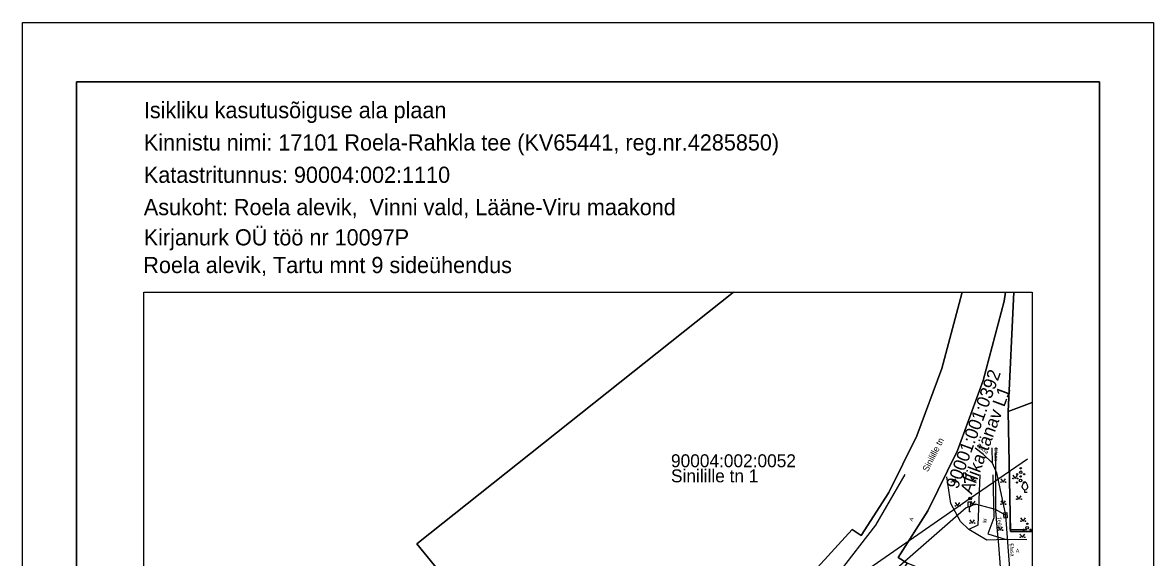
# Model space of a CAD drawing. Extents: x 648017 to 648227, y 6561313 to 6561610.
# Drawn here: x 648016.8 to 648226.8, y 6561510.6 to 6561609.9 of the extents above; entities that cross this region are included whole.
import ezdxf

# ---------------------------------------------------------------- set-up
doc = ezdxf.new("R2010")
doc.units = 0
for name, color, linetype in [('AED', 7, 'Continuous'), ('HALJASTUS', 7, 'Continuous'), ('KPOHULIIN', 7, 'Continuous'), ('LIIKLUS', 7, 'Continuous'), ('PIIR', 7, 'Continuous'), ('POST', 7, 'Continuous'), ('PR_SIDE', 7, 'Continuous'), ('PUU', 7, 'Continuous'), ('SIRAJATIS', 7, 'Continuous'), ('SITRASS', 7, 'Continuous'), ('TEE', 7, 'Continuous'), ('VORMISTUS', 7, 'Continuous')]:
    doc.layers.add(name, color=color, linetype=linetype)

msp = doc.modelspace()

# ---------------------------------------------------------------- linework, layer by layer
at = {"layer": 'AED'}
msp.add_lwpolyline([(648200.07, 6561526.28), (648200.12, 6561515.79), (648203.26, 6561515.79)], dxfattribs=at)
at = {"layer": 'HALJASTUS'}
for p, q in [((648200.65, 6561525.89), (648201.12, 6561525.28)), ((648201.12, 6561525.28), (648201.56, 6561525.89)), ((648189.19, 6561525.23), (648189.65, 6561524.63)), ((648189.65, 6561524.63), (648190.1, 6561525.23)), ((648192.79, 6561525.55), (648193.26, 6561524.94)), ((648193.26, 6561524.94), (648193.7, 6561525.55)), ((648198.42, 6561525.21), (648198.88, 6561524.61)), ((648198.88, 6561524.61), (648199.32, 6561525.21)), ((648201.35, 6561522.04), (648201.81, 6561521.44)), ((648201.81, 6561521.44), (648202.25, 6561522.04)), ((648189.94, 6561520.8), (648190.41, 6561520.19)), ((648190.41, 6561520.19), (648190.85, 6561520.8)), ((648192.79, 6561521.07), (648193.26, 6561520.47)), ((648193.26, 6561520.47), (648193.7, 6561521.07)), ((648198.42, 6561521.11), (648198.88, 6561520.51)), ((648198.88, 6561520.51), (648199.32, 6561521.11)), ((648192.68, 6561517.61), (648193.14, 6561517)), ((648193.14, 6561517), (648193.58, 6561517.61)), ((648202.12, 6561517.96), (648202.58, 6561517.36)), ((648202.58, 6561517.36), (648203.03, 6561517.96)), ((648197.86, 6561516.3), (648198.33, 6561515.69)), ((648198.33, 6561515.69), (648198.77, 6561516.3)), ((648202, 6561514.97), (648202.46, 6561514.37)), ((648202.46, 6561514.37), (648202.91, 6561514.97))]:
    msp.add_line(p, q, dxfattribs=at)
for centre in [(648189.25, 6561524.63), (648190.08, 6561524.63), (648192.86, 6561524.94), (648193.68, 6561524.94), (648198.48, 6561524.61), (648199.31, 6561524.61), (648200.72, 6561525.28), (648201.54, 6561525.28), (648201.41, 6561521.44), (648202.24, 6561521.44), (648190.01, 6561520.19), (648190.83, 6561520.19), (648192.86, 6561520.47), (648193.68, 6561520.47), (648198.48, 6561520.51), (648199.31, 6561520.51), (648202.18, 6561517.36), (648203.01, 6561517.36), (648192.74, 6561517), (648193.57, 6561517), (648197.92, 6561515.69), (648198.75, 6561515.69), (648202.06, 6561514.37), (648202.89, 6561514.37)]:
    msp.add_circle(centre, 0.055, dxfattribs=at)
at = {"layer": 'KPOHULIIN'}
msp.add_lwpolyline([(648203.38, 6561528.86), (648192.77, 6561521.55), (648147, 6561489.82)], dxfattribs=at)
at = {"layer": 'LIIKLUS'}
for p, q in [((648191.43, 6561526.29), (648191.43, 6561525.44)), ((648191.93, 6561526.29), (648191.43, 6561526.29)), ((648191.93, 6561526.29), (648191.93, 6561525.44)), ((648191.93, 6561525.44), (648191.43, 6561525.44)), ((648191.68, 6561525.44), (648191.68, 6561524.54)), ((648191.93, 6561524.54), (648191.68, 6561524.54)), ((648192.29, 6561520.86), (648192.29, 6561520.01)), ((648192.79, 6561520.86), (648192.29, 6561520.86)), ((648192.79, 6561520.01), (648192.29, 6561520.01)), ((648192.54, 6561520.01), (648192.54, 6561519.11)), ((648192.79, 6561520.86), (648192.79, 6561520.01)), ((648192.79, 6561519.11), (648192.54, 6561519.11))]:
    msp.add_line(p, q, dxfattribs=at)
at = {"layer": 'PIIR'}
for points in [[(648199.34, 6561559.88), (648199.07, 6561558.2), (648195.16, 6561543.45), (648190.37, 6561530.46), (648184.89, 6561519.28), (648179.37, 6561510.62), (648181.07, 6561509.57), (648180.15, 6561508.27), (648175.42, 6561502.2), (648170.88, 6561497.65), (648163.17, 6561490.84), (648148.46, 6561478.24), (648130.76, 6561463.29), (648079.41, 6561420.36), (648069.33, 6561411.95), (648039.27, 6561388.87)], [(648148.78, 6561559.88), (648090, 6561513.15), (648123.09, 6561472.56), (648039.27, 6561403.33)], [(648039.27, 6561403.33), (648123.09, 6561472.56), (648162.4, 6561506.57), (648170.84, 6561515.84), (648172.53, 6561514.72), (648177.65, 6561522.71), (648182.83, 6561533.2), (648187.47, 6561545.71), (648191.21, 6561559.62), (648191.24, 6561559.88)], [(648191.24, 6561559.88), (648191.21, 6561559.62), (648187.47, 6561545.71), (648182.83, 6561533.2), (648177.65, 6561522.71), (648172.53, 6561514.72), (648170.84, 6561515.84), (648162.4, 6561506.57), (648123.09, 6561472.56), (648090, 6561513.15), (648148.78, 6561559.88)], [(648204.28, 6561507.58), (648196.49, 6561507.4), (648190.43, 6561507.33), (648185.28, 6561507.91), (648181.07, 6561509.57), (648179.37, 6561510.62), (648184.89, 6561519.28), (648190.37, 6561530.46), (648195.16, 6561543.45), (648199.07, 6561558.2), (648199.34, 6561559.88)], [(648200.88, 6561559.88), (648199.82, 6561537.73), (648200.23, 6561515.42), (648204.28, 6561515.45)], [(648204.28, 6561539.37), (648199.82, 6561537.73), (648200.88, 6561559.88)], [(648204.28, 6561515.45), (648200.23, 6561515.42), (648199.82, 6561537.73), (648204.28, 6561539.37)]]:
    msp.add_lwpolyline(points, dxfattribs=at)
at = {"layer": 'POST'}
msp.add_circle((648192.77, 6561521.55), 0.25, dxfattribs=at)
at = {"layer": 'PR_SIDE'}
msp.add_lwpolyline([(648199.29, 6561518.48), (648197.48, 6561519.53), (648193.72, 6561520.51), (648192, 6561519.84), (648177.65, 6561507.26), (648164.45, 6561493.55), (648163.77, 6561492.92), (648154.87, 6561485.15), (648141.77, 6561473.44), (648118.71, 6561454.06), (648079.38, 6561420.99), (648069.19, 6561412.21), (648060.53, 6561403.42), (648044.66, 6561390.62), (648039.27, 6561386.53)], dxfattribs=at)
at = {"layer": 'PUU'}
for p, q in [((648202.93, 6561522.7), (648202.93, 6561523.2)), ((648203.33, 6561522.7), (648202.93, 6561522.7))]:
    msp.add_line(p, q, dxfattribs=at)
for points in [[(648202.43, 6561523.7), (648202.43, 6561523.85), (648202.44, 6561523.92), (648202.47, 6561524.05), (648202.53, 6561524.17), (648202.68, 6561524.4), (648202.84, 6561524.61), (648202.93, 6561524.7)], [(648203.43, 6561523.7), (648203.43, 6561523.85), (648203.42, 6561523.92), (648203.38, 6561524.05), (648203.32, 6561524.17), (648203.18, 6561524.4), (648203.02, 6561524.61), (648202.93, 6561524.7)]]:
    msp.add_lwpolyline(points, dxfattribs=at)
for centre, radius in [((648201.48, 6561526.06), 0.125), ((648202.13, 6561526.43), 0.25), ((648202.13, 6561527.18), 0.125), ((648202.12, 6561525.67), 0.125), ((648202.78, 6561526.06), 0.125), ((648201.47, 6561524.54), 0.125), ((648202.12, 6561524.92), 0.25), ((648202.77, 6561524.54), 0.125), ((648202.7, 6561515.77), 0.125), ((648203.35, 6561516.14), 0.25), ((648203.35, 6561516.89), 0.125), ((648204, 6561515.77), 0.125)]:
    msp.add_circle(centre, radius, dxfattribs=at)
msp.add_arc((648202.93, 6561523.7), 0.5, 180, 0, dxfattribs=at)
at = {"layer": 'SIRAJATIS'}
msp.add_lwpolyline([(648199.55, 6561518.99), (648199.65, 6561518), (648199.05, 6561517.94), (648198.95, 6561518.93)], close=True, dxfattribs=at)
for centre, radius in [((648199.28, 6561518.66), 0.0304), ((648199.28, 6561518.66), 0.029), ((648199.28, 6561518.66), 0.0277), ((648199.28, 6561518.66), 0.0263), ((648199.28, 6561518.66), 0.0249), ((648199.28, 6561518.66), 0.0236), ((648199.28, 6561518.66), 0.0222), ((648199.28, 6561518.66), 0.0209), ((648199.28, 6561518.66), 0.0195), ((648199.28, 6561518.66), 0.0181), ((648199.28, 6561518.66), 0.0168), ((648199.28, 6561518.66), 0.0154), ((648199.28, 6561518.66), 0.014), ((648199.28, 6561518.66), 0.0127), ((648199.28, 6561518.66), 0.0113), ((648199.28, 6561518.66), 0.00996), ((648199.28, 6561518.66), 0.0086), ((648199.28, 6561518.66), 0.00724), ((648199.28, 6561518.66), 0.00587), ((648199.28, 6561518.66), 0.00451), ((648199.28, 6561518.66), 0.00315), ((648199.28, 6561518.66), 0.00179), ((648199.28, 6561518.66), 0.000426), ((648199.32, 6561518.27), 0.0304), ((648199.32, 6561518.27), 0.029), ((648199.32, 6561518.27), 0.0277), ((648199.32, 6561518.27), 0.0263), ((648199.32, 6561518.27), 0.0249), ((648199.32, 6561518.27), 0.0236), ((648199.32, 6561518.27), 0.0222), ((648199.32, 6561518.27), 0.0209), ((648199.32, 6561518.27), 0.0195), ((648199.32, 6561518.27), 0.0181), ((648199.32, 6561518.27), 0.0168), ((648199.32, 6561518.27), 0.0154), ((648199.32, 6561518.27), 0.014), ((648199.32, 6561518.27), 0.0127), ((648199.32, 6561518.27), 0.0113), ((648199.32, 6561518.27), 0.00996), ((648199.32, 6561518.27), 0.0086), ((648199.32, 6561518.27), 0.00724), ((648199.32, 6561518.27), 0.00587), ((648199.32, 6561518.27), 0.00451), ((648199.32, 6561518.27), 0.00315), ((648199.32, 6561518.27), 0.00179), ((648199.32, 6561518.27), 0.000426)]:
    msp.add_circle(centre, radius, dxfattribs=at)
at = {"layer": 'SITRASS'}
for points in [[(648196.82, 6561528.19), (648195.23, 6561529.71), (648193.69, 6561530.93)], [(648196.79, 6561530.96), (648196.79, 6561530.92), (648196.82, 6561528.19), (648197.62, 6561526.36), (648199.29, 6561518.48)], [(648197.51, 6561531.02), (648197.44, 6561528.85), (648197.46, 6561525.3), (648197.48, 6561519.33), (648197.72, 6561516.25), (648197.99, 6561512.88), (648198.52, 6561506.41), (648198.57, 6561505.82), (648198.85, 6561495.75)], [(648199.29, 6561518.48), (648199.79, 6561511.82), (648200.2, 6561506.99), (648200.68, 6561503.04)], [(648199.29, 6561518.48), (648199.79, 6561511.82), (648200.2, 6561506.99), (648200.68, 6561503.04), (648201.26, 6561501.84), (648203.37, 6561501.74)]]:
    msp.add_lwpolyline(points, dxfattribs=at)
at = {"layer": 'TEE'}
for points in [[(648180.64, 6561526.05), (648175.16, 6561516.61), (648168.19, 6561507.6), (648157.52, 6561497.62), (648149.94, 6561491.11), (648138.91, 6561481.66), (648130.58, 6561474.7), (648128.76, 6561474.38)], [(648203.26, 6561513.88), (648199.46, 6561513.95), (648195.82, 6561513.83), (648192.49, 6561515.81), (648190.93, 6561517.28), (648189.17, 6561520.66), (648188.43, 6561525.61)], [(648194.57, 6561525.97), (648194.19, 6561516.64), (648192.49, 6561515.81)], [(648196.96, 6561525.95), (648197.12, 6561517.96), (648196.06, 6561515.01), (648199.46, 6561513.95)]]:
    msp.add_lwpolyline(points, dxfattribs=at)
at = {"layer": 'VORMISTUS'}
for points in [[(648016.78, 6561609.88), (648226.78, 6561609.88), (648226.78, 6561312.88), (648016.78, 6561312.88)], [(648026.78, 6561323.88), (648216.78, 6561323.88), (648216.78, 6561598.88), (648026.78, 6561598.88)], [(648026.78, 6561598.88), (648216.78, 6561598.88), (648216.78, 6561323.88), (648026.78, 6561323.88)], [(648204.28, 6561349.88), (648039.27, 6561349.88), (648039.27, 6561559.88), (648204.28, 6561559.88)]]:
    msp.add_lwpolyline(points, close=True, dxfattribs=at)

# ---------------------------------------------------------------- texts
at = {"layer": 'PIIR'}
for s, p in [('90001:001:0392', (648190.43, 6561523.17)), ('Allika tänav L1', (648193.05, 6561522.2))]:
    msp.add_text(s, height=2.4, rotation=69.664, dxfattribs=at).set_placement(p)
for s, p in [('90004:002:0052', (648137.19, 6561527.37)), ('Sinilille tn 1', (648137.19, 6561524.57))]:
    msp.add_text(s, height=2.4, dxfattribs=at).set_placement(p)
at = {"layer": 'SITRASS'}
for s, rotation, p in [('Elasa', 321.7248, (648193.95, 6561531.26)), ('Elasa', 270.4571, (648197.21, 6561530.93)), ('Telia', 274.3701, (648197.79, 6561518.17)), ('Elasa', 274.8273, (648200.08, 6561513.21))]:
    msp.add_text(s, height=0.7, rotation=rotation, dxfattribs=at).set_placement(p)
at = {"layer": 'TEE'}
for s, height, rotation, p in [('Sinilille tn', 1.2, 63.1899, (648184.88, 6561526.41)), ('A', 0.7, 64.6008, (648182.02, 6561517.26)), ('kr', 0.7, 89.9544, (648195.8, 6561517.1)), ('A', 0.7, 359.9544, (648201.23, 6561511.54))]:
    msp.add_text(s, height=height, rotation=rotation, dxfattribs=at).set_placement(p)
at = {"layer": 'VORMISTUS'}
for s, p in [('Isikliku kasutusõiguse ala plaan', (648039.29, 6561592.15)), ('Kinnistu nimi: 17101 Roela-Rahkla tee (KV65441, reg.nr.4285850)', (648039.29, 6561586.15)), ('Katastritunnus: 90004:002:1110', (648039.29, 6561580.15)), ('Asukoht: Roela alevik,  Vinni vald, Lääne-Viru maakond', (648039.29, 6561574.15))]:
    msp.add_text(s, height=3, dxfattribs=at).set_placement(p)
for s, p in [('Kirjanurk OÜ töö nr 10097P', (648039.27, 6561568.54)), ('Roela alevik, Tartu mnt 9 sideühendus', (648039.19, 6561563.4))]:
    msp.add_text(s, height=3, rotation=360, dxfattribs=at).set_placement(p)

doc.saveas('drawing.dxf')
